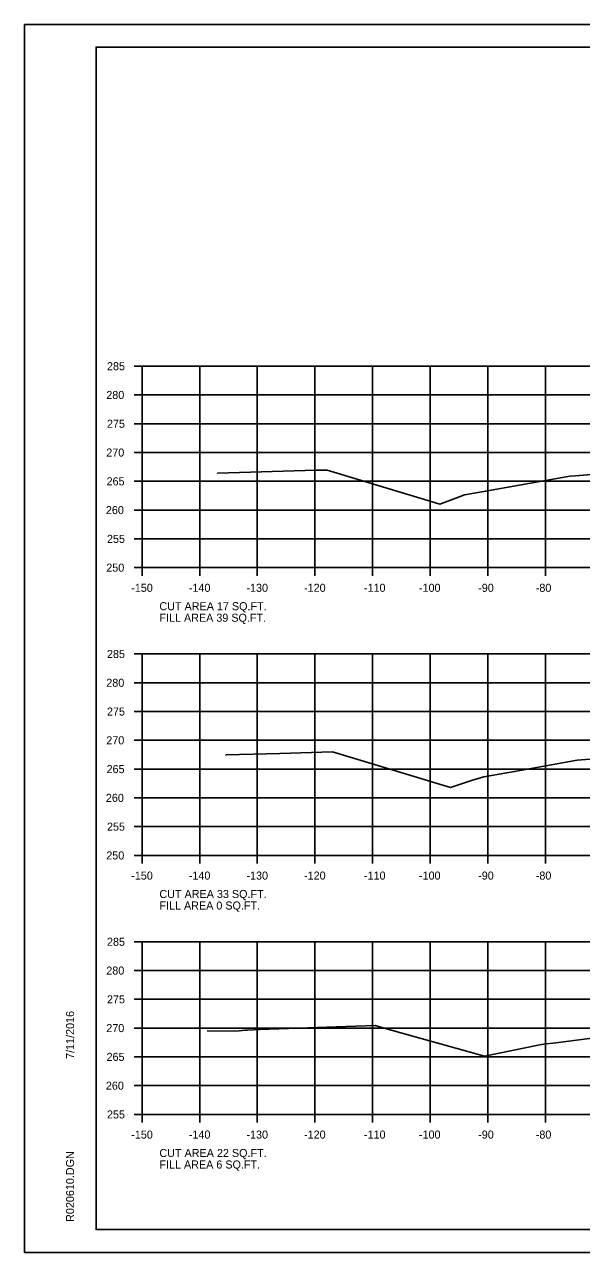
# Model space of a CAD drawing. Extents: x 1103485 to 1107180, y 2010593 to 2011873.
# Drawn here: x 1106846.8 to 1106943.4, y 2010806.2 to 2011019.5 of the extents above; entities that cross this region are included whole.
import ezdxf

# ---------------------------------------------------------------- set-up
doc = ezdxf.new("R2010")
doc.units = 0
for name, color, linetype in [('R_Axis', 7, 'Continuous'), ('R_Axis Annot', 7, 'Continuous'), ('R_Border', 7, 'Continuous'), ('R_Exist Surface', 7, 'Continuous'), ('R_Grid', 7, 'Continuous'), ('R_No Plot', 7, 'Continuous')]:
    doc.layers.add(name, color=color, linetype=linetype)

msp = doc.modelspace()

# ---------------------------------------------------------------- linework, layer by layer
at = {"layer": 'R_Axis'}
for p, q in [((1106865.78, 2010960.15), (1106867.18, 2010960.15)), ((1106867.18, 2010925.15), (1106867.18, 2010960.15)), ((1106865.78, 2010955.15), (1106867.18, 2010955.15)), ((1106865.78, 2010950.15), (1106867.18, 2010950.15)), ((1106865.78, 2010945.15), (1106867.18, 2010945.15)), ((1106865.78, 2010940.15), (1106867.18, 2010940.15)), ((1106865.78, 2010935.15), (1106867.18, 2010935.15)), ((1106865.78, 2010930.15), (1106867.18, 2010930.15)), ((1106865.78, 2010925.15), (1106867.18, 2010925.15)), ((1106867.18, 2010925.15), (1107167.18, 2010925.15)), ((1106867.18, 2010923.75), (1106867.18, 2010925.15)), ((1106877.18, 2010923.75), (1106877.18, 2010925.15)), ((1106887.18, 2010923.75), (1106887.18, 2010925.15)), ((1106897.18, 2010923.75), (1106897.18, 2010925.15)), ((1106907.18, 2010923.75), (1106907.18, 2010925.15)), ((1106917.18, 2010923.75), (1106917.18, 2010925.15)), ((1106927.18, 2010923.75), (1106927.18, 2010925.15)), ((1106937.18, 2010923.75), (1106937.18, 2010925.15)), ((1106865.78, 2010910.15), (1106867.18, 2010910.15)), ((1106867.18, 2010875.15), (1106867.18, 2010910.15)), ((1106865.78, 2010905.15), (1106867.18, 2010905.15)), ((1106865.78, 2010900.15), (1106867.18, 2010900.15)), ((1106865.78, 2010895.15), (1106867.18, 2010895.15)), ((1106865.78, 2010890.15), (1106867.18, 2010890.15)), ((1106865.78, 2010885.15), (1106867.18, 2010885.15)), ((1106865.78, 2010880.15), (1106867.18, 2010880.15)), ((1106865.78, 2010875.15), (1106867.18, 2010875.15)), ((1106867.18, 2010875.15), (1107167.18, 2010875.15)), ((1106867.18, 2010873.75), (1106867.18, 2010875.15)), ((1106877.18, 2010873.75), (1106877.18, 2010875.15)), ((1106887.18, 2010873.75), (1106887.18, 2010875.15)), ((1106897.18, 2010873.75), (1106897.18, 2010875.15)), ((1106907.18, 2010873.75), (1106907.18, 2010875.15)), ((1106917.18, 2010873.75), (1106917.18, 2010875.15)), ((1106927.18, 2010873.75), (1106927.18, 2010875.15)), ((1106937.18, 2010873.75), (1106937.18, 2010875.15)), ((1106865.78, 2010860.15), (1106867.18, 2010860.15)), ((1106867.18, 2010830.15), (1106867.18, 2010860.15)), ((1106865.78, 2010855.15), (1106867.18, 2010855.15)), ((1106865.78, 2010850.15), (1106867.18, 2010850.15)), ((1106865.78, 2010845.15), (1106867.18, 2010845.15)), ((1106865.78, 2010840.15), (1106867.18, 2010840.15)), ((1106865.78, 2010835.15), (1106867.18, 2010835.15)), ((1106865.78, 2010830.15), (1106867.18, 2010830.15)), ((1106867.18, 2010830.15), (1107167.18, 2010830.15)), ((1106867.18, 2010828.75), (1106867.18, 2010830.15)), ((1106877.18, 2010828.75), (1106877.18, 2010830.15)), ((1106887.18, 2010828.75), (1106887.18, 2010830.15)), ((1106897.18, 2010828.75), (1106897.18, 2010830.15)), ((1106907.18, 2010828.75), (1106907.18, 2010830.15)), ((1106917.18, 2010828.75), (1106917.18, 2010830.15)), ((1106927.18, 2010828.75), (1106927.18, 2010830.15)), ((1106937.18, 2010828.75), (1106937.18, 2010830.15))]:
    msp.add_line(p, q, dxfattribs=at)
at = {"layer": 'R_Border'}
for p, q in [((1106859.18, 2011015.61), (1107175.36, 2011015.61)), ((1106859.18, 2010810.15), (1106859.18, 2011015.61)), ((1106859.18, 2010810.15), (1106859.18, 2010810.15)), ((1107175.36, 2010810.15), (1106859.18, 2010810.15))]:
    msp.add_line(p, q, dxfattribs=at)
at = {"layer": 'R_Exist Surface'}
for points in [[(1106880.22, 2010941.49), (1106880.27, 2010941.54), (1106897.38, 2010942.06), (1106899.32, 2010942.11), (1106917.35, 2010936.62), (1106918.86, 2010936.16), (1106922.09, 2010937.41), (1106923.12, 2010937.81), (1106926.14, 2010938.34), (1106939.79, 2010940.74), (1106941.44, 2010941.03), (1106942.4, 2010941.11), (1106949.81, 2010941.74)], [(1106881.67, 2010892.51), (1106881.79, 2010892.62), (1106891.11, 2010892.86), (1106900.23, 2010893.13), (1106912.48, 2010889.42), (1106920.71, 2010886.94), (1106924.53, 2010888.24), (1106926.52, 2010888.82), (1106931.81, 2010889.74), (1106942.7, 2010891.69), (1106946.49, 2010892)], [(1106878.47, 2010844.68), (1106883.43, 2010844.63), (1106885.15, 2010844.79), (1106885.21, 2010844.8), (1106885.39, 2010844.81), (1106887.56, 2010844.92), (1106907.62, 2010845.61), (1106909.59, 2010845.04), (1106926.61, 2010840.27), (1106935.93, 2010842.17), (1106936.87, 2010842.35), (1106939, 2010842.61), (1106947.97, 2010843.77)]]:
    msp.add_lwpolyline(points, dxfattribs=at)
at = {"layer": 'R_Grid'}
for p, q in [((1106867.18, 2010960.15), (1107167.18, 2010960.15)), ((1106867.18, 2010925.15), (1106867.18, 2010960.15)), ((1106877.18, 2010925.15), (1106877.18, 2010960.15)), ((1106887.18, 2010925.15), (1106887.18, 2010960.15)), ((1106897.18, 2010925.15), (1106897.18, 2010960.15)), ((1106907.18, 2010925.15), (1106907.18, 2010960.15)), ((1106917.18, 2010925.15), (1106917.18, 2010960.15)), ((1106927.18, 2010925.15), (1106927.18, 2010960.15)), ((1106937.18, 2010925.15), (1106937.18, 2010960.15)), ((1106867.18, 2010955.15), (1107167.18, 2010955.15)), ((1106867.18, 2010950.15), (1107167.18, 2010950.15)), ((1106867.18, 2010945.15), (1107167.18, 2010945.15)), ((1106867.18, 2010940.15), (1107167.18, 2010940.15)), ((1106867.18, 2010935.15), (1107167.18, 2010935.15)), ((1106867.18, 2010930.15), (1107167.18, 2010930.15)), ((1106867.18, 2010925.15), (1107167.18, 2010925.15)), ((1106867.18, 2010910.15), (1107167.18, 2010910.15)), ((1106867.18, 2010875.15), (1106867.18, 2010910.15)), ((1106877.18, 2010875.15), (1106877.18, 2010910.15)), ((1106887.18, 2010875.15), (1106887.18, 2010910.15)), ((1106897.18, 2010875.15), (1106897.18, 2010910.15)), ((1106907.18, 2010875.15), (1106907.18, 2010910.15)), ((1106917.18, 2010875.15), (1106917.18, 2010910.15)), ((1106927.18, 2010875.15), (1106927.18, 2010910.15)), ((1106937.18, 2010875.15), (1106937.18, 2010910.15)), ((1106867.18, 2010905.15), (1107167.18, 2010905.15)), ((1106867.18, 2010900.15), (1107167.18, 2010900.15)), ((1106867.18, 2010895.15), (1107167.18, 2010895.15)), ((1106867.18, 2010890.15), (1107167.18, 2010890.15)), ((1106867.18, 2010885.15), (1107167.18, 2010885.15)), ((1106867.18, 2010880.15), (1107167.18, 2010880.15)), ((1106867.18, 2010875.15), (1107167.18, 2010875.15)), ((1106867.18, 2010860.15), (1107167.18, 2010860.15)), ((1106867.18, 2010830.15), (1106867.18, 2010860.15)), ((1106877.18, 2010830.15), (1106877.18, 2010860.15)), ((1106887.18, 2010830.15), (1106887.18, 2010860.15)), ((1106897.18, 2010830.15), (1106897.18, 2010860.15)), ((1106907.18, 2010830.15), (1106907.18, 2010860.15)), ((1106917.18, 2010830.15), (1106917.18, 2010860.15)), ((1106927.18, 2010830.15), (1106927.18, 2010860.15)), ((1106937.18, 2010830.15), (1106937.18, 2010860.15)), ((1106867.18, 2010855.15), (1107167.18, 2010855.15)), ((1106867.18, 2010850.15), (1107167.18, 2010850.15)), ((1106867.18, 2010845.15), (1107167.18, 2010845.15)), ((1106867.18, 2010840.15), (1107167.18, 2010840.15)), ((1106867.18, 2010835.15), (1107167.18, 2010835.15)), ((1106867.18, 2010830.15), (1107167.18, 2010830.15))]:
    msp.add_line(p, q, dxfattribs=at)
at = {"layer": 'R_No Plot'}
for p, q in [((1106846.78, 2011019.51), (1107180.12, 2011019.51)), ((1106846.78, 2010806.18), (1107180.12, 2010806.18))]:
    msp.add_line(p, q, dxfattribs=at)
for points in [[(1106846.78, 2011019.51), (1107180.12, 2011019.51), (1107180.12, 2010806.17), (1106846.78, 2010806.17)], [(1107093.1, 2011015.61), (1107093.1, 2011005.73), (1107128.84, 2011005.73), (1107128.84, 2011002.81), (1107152.04, 2011002.81), (1107152.04, 2010978.48), (1107175.36, 2010978.48), (1107175.36, 2010810.15), (1106859.18, 2010810.15), (1106859.18, 2011015.61)]]:
    msp.add_lwpolyline(points, close=True, dxfattribs=at)

# ---------------------------------------------------------------- texts
at = {"layer": 'R_Axis Annot'}
for s, p in [('285', (1106861.08, 2010959.45)), ('280', (1106860.96, 2010954.45)), ('275', (1106861.08, 2010949.45)), ('270', (1106860.96, 2010944.45)), ('265', (1106861.01, 2010939.45)), ('260', (1106860.89, 2010934.45)), ('255', (1106861.08, 2010929.45)), ('250', (1106860.96, 2010924.45)), ('-150', (1106865.29, 2010920.95)), ('-140', (1106875.29, 2010920.95)), ('-130', (1106885.29, 2010920.95)), ('-120', (1106895.29, 2010920.95)), ('-110', (1106905.69, 2010920.95)), ('-100', (1106915.24, 2010920.95)), ('-90', (1106925.52, 2010920.95)), ('-80', (1106935.52, 2010920.95)), ('CUT AREA 17 SQ.FT.', (1106870.18, 2010917.75)), ('FILL AREA 39 SQ.FT.', (1106870.18, 2010915.75)), ('285', (1106861.08, 2010909.45)), ('280', (1106860.96, 2010904.45)), ('275', (1106861.08, 2010899.45)), ('270', (1106860.96, 2010894.45)), ('265', (1106861.01, 2010889.45)), ('260', (1106860.89, 2010884.45)), ('255', (1106861.08, 2010879.45)), ('250', (1106860.96, 2010874.45)), ('-150', (1106865.29, 2010870.95)), ('-140', (1106875.29, 2010870.95)), ('-130', (1106885.29, 2010870.95)), ('-120', (1106895.29, 2010870.95)), ('-110', (1106905.69, 2010870.95)), ('-100', (1106915.24, 2010870.95)), ('-90', (1106925.52, 2010870.95)), ('-80', (1106935.52, 2010870.95)), ('CUT AREA 33 SQ.FT.', (1106870.18, 2010867.75)), ('FILL AREA 0 SQ.FT.', (1106870.18, 2010865.75)), ('285', (1106861.08, 2010859.45)), ('280', (1106860.96, 2010854.45)), ('275', (1106861.08, 2010849.45)), ('270', (1106860.96, 2010844.45)), ('265', (1106861.01, 2010839.45)), ('260', (1106860.89, 2010834.45)), ('255', (1106861.08, 2010829.45)), ('-150', (1106865.29, 2010825.95)), ('-140', (1106875.29, 2010825.95)), ('-130', (1106885.29, 2010825.95)), ('-120', (1106895.29, 2010825.95)), ('-110', (1106905.69, 2010825.95)), ('-100', (1106915.24, 2010825.95)), ('-90', (1106925.52, 2010825.95)), ('-80', (1106935.52, 2010825.95)), ('CUT AREA 22 SQ.FT.', (1106870.18, 2010822.75)), ('FILL AREA 6 SQ.FT.', (1106870.18, 2010820.75))]:
    msp.add_text(s, height=1.4, dxfattribs=at).set_placement(p)
at = {"layer": 'R_Border'}
for s, p in [('7/11/2016', (1106855.37, 2010839.8)), ('R020610.DGN', (1106855.37, 2010811.48))]:
    msp.add_text(s, height=1.4, rotation=90, dxfattribs=at).set_placement(p)

doc.saveas('drawing.dxf')
